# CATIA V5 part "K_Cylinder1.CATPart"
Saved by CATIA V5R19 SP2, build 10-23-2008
Part number: Liant1
Bounding box of the stored display mesh (mm): x 0 to 4, y -2 to 2, z -2 to 2
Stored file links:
  G:\Khaled_CFAO_2011\ST2M\ST2M_GR1\bgaltie\bgaltie\Khaled\CAD_thinkMOTION\K_Cylinder1.CATPart
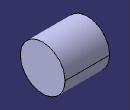
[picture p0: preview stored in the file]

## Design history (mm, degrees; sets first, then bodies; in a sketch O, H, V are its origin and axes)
AxisSystem1: origin (0, 0, 0), X (1, 0, 0), Y (0, 1, 0), Z (0, 0, 1)
Body1 (main body)
  Sketch1 on YZ plane of AxisSystem1, origin (0, 0, 0), H (0, 1, 0), V (0, 0, 1)
    circle A1 centre (0, 0) radius 2
    point P1 (0, 0)
    radius A1 = 2
    coincidence: P1 O
  Pad1: profile Sketch1, direction (1, 0, 0), length 4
